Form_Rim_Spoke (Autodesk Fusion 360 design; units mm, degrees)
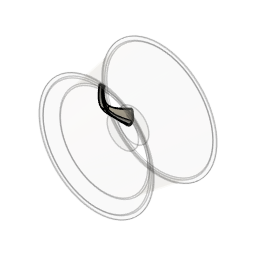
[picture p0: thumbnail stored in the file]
part number: 2026-08-31-11-24-50-377
sketch "Sketch1" plane through (0, 0, 0) normal (1, 0, 0) x axis (0, 1, 0)
  line L1 (12.5, 0) -> (-12.5, 0)
  line L2 (-76.2, 127) -> (-77.0749, 137)
  line L3 (0, 127) -> (-76.2, 127)
  line L4 (0, 0) -> (0, 127)
  line L5 (76.2, 127) -> (77.0749, 137)
  line L6 (0, 127) -> (76.2, 127)
  line L7 (-73.9092, 129.5) -> (-74.5844, 137.2179)
  line L8 (0, 129.5) -> (-73.9092, 129.5)
  line L9 (0, 129.5) -> (73.9092, 129.5)
  line L10 (73.9092, 129.5) -> (74.5844, 137.2179)
  line L11 (74.5844, 137.2179) -> (77.0749, 137)
  line L12 (-74.5844, 137.2179) -> (-77.0749, 137)
  line L13 (-12.5, 37.5) -> (-12.5, 0)
  line L14 (12.5, 37.5) -> (-12.5, 37.5)
  line L15 (12.5, 0) -> (12.5, 37.5)
  line L16 (-57.3203, 104.5) -> (-76.2, 127)
  line L17 (76.2, 127) -> (-57.3203, 104.5)
  line L18 (-55.597, 107.6764) -> (-73.9092, 129.5)
  line L19 (73.9092, 129.5) -> (-55.597, 107.6764)
  point P4 (0, 0)
  point P1 (0, 0)
  point P8 (0, 0)
  point P5 (-77.0749, 137)
  point P9 (77.0749, 137)
  point P6 (-76.2, 127)
  point P10 (76.2, 127)
  point P7 (0, 127)
  point P11 (0, 127)
  point P2 (-12.5, 0)
  point P3 (12.5, 0)
  point P19 (-57.3203, 104.5)
  midpoint L1 P4
  coincident P1 P4
  horizontal L1
  horizontal L3
  coincident P4 P8
  vertical L4
  symmetric P5 L4 P9
  symmetric P6 L4 P10
  symmetric P7 L4 P11
  perpendicular L10 L11
  perpendicular L7 L12
  perpendicular L1 L13
  perpendicular L13 L14
  perpendicular L1 L15
  parallel L16 L18
  parallel L17 L19
  dimension "d1" distance P2 P3 = 25
  dimension "d2" = 254
  dimension "d3" distance P6 L4 = 76.2
  dimension "d4" distance P5 L3 = 10
  dimension "d5" angle L2 L3 = 95
  dimension "d6" = 2.5
  dimension "d7" = 75
  dimension "d9" angle L8 L16 = 130
  dimension "d10" distance L8 P19 = 25
revolve "Revolve1" sketch "Sketch1" AlongAngle 360
form "Form1"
